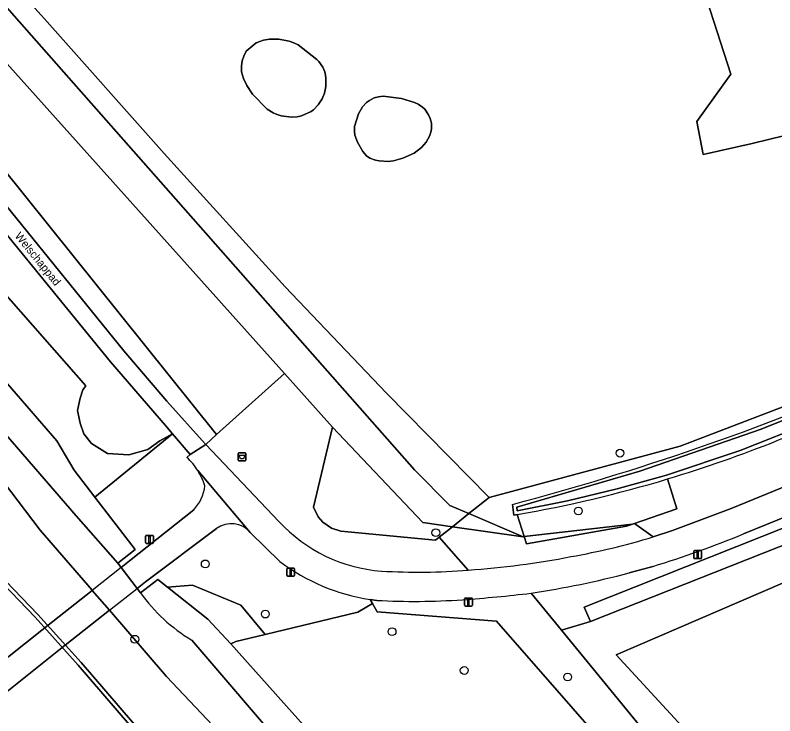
# Model space of a CAD drawing. Extents: x 156061 to 157804, y 383437 to 385640.
# Drawn here: x 157340 to 157434.9, y 383885.8 to 383973.3 of the extents above; entities that cross this region are included whole.
import ezdxf

# ---------------------------------------------------------------- set-up
doc = ezdxf.new("R2010")
doc.units = 0
for name, color, linetype in [('IMGEO_Afvalbak', 7, 'Continuous'), ('IMGEO_Berm_groen', 7, 'Continuous'), ('IMGEO_Boom', 7, 'Continuous'), ('IMGEO_Dek', 7, 'Continuous'), ('IMGEO_Fietspad_gesloten', 7, 'Continuous'), ('IMGEO_Fietspad_halfverhard', 7, 'Continuous'), ('IMGEO_Gemengd_bos', 7, 'Continuous'), ('IMGEO_Grasland_overig', 7, 'Continuous'), ('IMGEO_Groenvoorziening', 7, 'Continuous'), ('IMGEO_Hek', 7, 'Continuous'), ('IMGEO_Kademuur', 7, 'Continuous'), ('IMGEO_Lichtmast', 7, 'Continuous'), ('IMGEO_Loofbos', 7, 'Continuous'), ('IMGEO_Naaldbos', 7, 'Continuous'), ('IMGEO_Oever', 7, 'Continuous'), ('IMGEO_Openbare_ruimte_label', 7, 'Continuous'), ('IMGEO_Terreindeel_zand', 7, 'Continuous'), ('IMGEO_Waterloop', 7, 'Continuous')]:
    doc.layers.add(name, color=color, linetype=linetype)

msp = doc.modelspace()

# ---------------------------------------------------------------- linework, layer by layer
at = {"layer": 'IMGEO_Afvalbak'}
for p, q in [((157367.87, 383917.721), (157367.87, 383918.521)), ((157367.87, 383918.521), (157367.87, 383917.721)), ((157367.97, 383918.621), (157368.76, 383918.621)), ((157368.76, 383918.621), (157367.97, 383918.621)), ((157368.86, 383918.521), (157368.86, 383917.721)), ((157368.86, 383917.721), (157368.86, 383918.521)), ((157368.76, 383917.621), (157367.97, 383917.621)), ((157367.97, 383917.621), (157368.76, 383917.621))]:
    msp.add_line(p, q, dxfattribs=at)
msp.add_lwpolyline([(157368.013, 383918.335), (157368.717, 383918.335), (157368.568, 383917.865), (157368.162, 383917.865), (157368.013, 383918.335)], dxfattribs=at)
for centre, start, end in [((157367.97, 383918.521), 90, 180), ((157367.97, 383918.521), 90, 180), ((157368.76, 383918.521), 0, 90), ((157368.76, 383918.521), 360, 90), ((157367.97, 383917.721), 180, 270), ((157367.97, 383917.721), 180, 270), ((157368.76, 383917.721), 270, 0), ((157368.76, 383917.721), 270, 0)]:
    msp.add_arc(centre, 0.1, start, end, dxfattribs=at)
at = {"layer": 'IMGEO_Berm_groen'}
for points in [[(157290.106, 383993.809), (157348.861, 383926.973), (157348.496, 383926.485), (157348.148, 383925.443), (157347.803, 383923.91), (157348.13, 383922.337), (157348.587, 383921.007), (157349.58, 383919.805), (157351.567, 383918.549), (157354.208, 383918.372), (157356.584, 383919.046), (157358.1, 383920.118), (157359.668, 383920.985), (157358.8, 383922.017), (157351.927, 383929.987), (157331.108, 383955.485)], [(157517.733, 383943.702), (157500, 383936.506), (157462.003, 383921.087), (157431.048, 383908.507)], [(157421.548, 383915.365), (157422.713, 383911.64), (157417.276, 383909.769), (157417.146, 383909.724), (157417.419, 383909.786), (157419.731, 383908.129), (157422.151, 383908.928), (157429.498, 383911.684), (157449.933, 383920.053), (157500, 383940.38)], [(157404.491, 383901.096), (157408.277, 383896.475), (157411.901, 383897.544), (157411.136, 383899.333), (157500, 383934.673)], [(157419.699, 383904.431), (157416.735, 383903.615)]]:
    msp.add_lwpolyline(points, dxfattribs=at)
for centre, radius, start, end in [((157374.531, 384071.809), 163.356, 286.7274, 296.96883), ((157381.602, 384028.345), 129.639, 287.09005, 292.42152), ((157386.751, 384018.341), 118.579, 278.60403, 284.64687)]:
    msp.add_arc(centre, radius, start, end, dxfattribs=at)
at = {"layer": 'IMGEO_Boom'}
for centre in [(157415.602, 383918.588), (157410.384, 383911.353), (157392.578, 383908.65), (157363.773, 383904.747), (157371.281, 383898.483), (157387.117, 383896.285), (157354.975, 383895.338), (157396.133, 383891.442), (157409.055, 383890.62)]:
    msp.add_circle(centre, 0.489, dxfattribs=at)
at = {"layer": 'IMGEO_Dek'}
msp.add_lwpolyline([(157337.095, 383887.331), (157345.496, 383893.968), (157351.807, 383898.954), (157355.264, 383901.686), (157353.281, 383904.309), (157349.655, 383901.447), (157343.336, 383896.46), (157334.933, 383889.827), (157335.95, 383888.66)], close=True, dxfattribs=at)
at = {"layer": 'IMGEO_Fietspad_gesloten'}
for points in [[(157524.621, 383950.374), (157500, 383940.38), (157449.933, 383920.053), (157429.498, 383911.684), (157422.151, 383908.928), (157419.731, 383908.129)], [(157431.048, 383908.507), (157462.003, 383921.087), (157500, 383936.506)], [(157372.986, 383910.034), (157363.833, 383919.682), (157361.887, 383918.404), (157361.489, 383918.054)], [(157369.409, 383908.645), (157369.386, 383908.678), (157362.833, 383916.407)], [(157362.833, 383916.407), (157369.386, 383908.678), (157369.409, 383908.645), (157373.088, 383905.055)], [(157362.326, 383911.521), (157354.325, 383905.133), (157353.281, 383904.309), (157355.264, 383901.686), (157356.301, 383902.505), (157365.179, 383909.17)], [(157416.735, 383903.615), (157419.699, 383904.431)], [(157384.365, 383900.302), (157385.206, 383900.193)]]:
    msp.add_lwpolyline(points, dxfattribs=at)
msp.add_lwpolyline([(157337.095, 383887.331), (157345.496, 383893.968), (157351.807, 383898.954), (157355.264, 383901.686), (157353.281, 383904.309), (157349.655, 383901.447), (157343.336, 383896.46), (157334.933, 383889.827), (157335.95, 383888.66)], close=True, dxfattribs=at)
for centre, radius, start, end in [((157355.53, 383911.82), 8.624, 32.13573, 46.29516), ((157355.486, 383911.781), 8.682, 18.1348, 32.19859), ((157358.595, 383915.115), 5.181, 316.06818, 352.98861), ((157367.018, 383906.685), 3.092, 39.34518, 126.50482), ((157387.304, 383923.334), 19.542, 222.88964, 265.59021), ((157395.45, 383986.551), 82.095, 279.82457, 287.20359), ((157381.602, 384028.345), 129.639, 287.09005, 292.42152), ((157388.102, 383924.923), 24.903, 232.92198, 261.36938), ((157389.641, 384006.873), 103.135, 273.89195, 281.07825), ((157390.319, 383981.535), 77.816, 266.67172, 274.66019), ((157386.751, 384018.341), 118.579, 278.60403, 284.64687), ((157383.208, 384078.229), 178.408, 274.07957, 276.85145), ((157389.883, 383988.669), 88.599, 266.97395, 273.89399)]:
    msp.add_arc(centre, radius, start, end, dxfattribs=at)
at = {"layer": 'IMGEO_Fietspad_halfverhard'}
msp.add_lwpolyline([(157237.284, 384056.657), (157244.448, 384048.492), (157247.832, 384044.707), (157258.966, 384032.481), (157270.566, 384020.689), (157270.958, 384020.289), (157290.747, 384000.096), (157290.837, 384000), (157295.593, 383994.904), (157306.477, 383982.754), (157317.899, 383970.658), (157322.769, 383965.414), (157327.304, 383960.078), (157331.108, 383955.485), (157351.927, 383929.987), (157358.8, 383922.017), (157359.668, 383920.985), (157361.887, 383918.404), (157363.833, 383919.682), (157363.756, 383919.763), (157358.967, 383925.076), (157353.604, 383931.382), (157332.793, 383957.006), (157329.258, 383961.307)], dxfattribs=at)
at = {"layer": 'IMGEO_Gemengd_bos'}
msp.add_lwpolyline([(157361.489, 383918.054), (157361.887, 383918.404), (157359.668, 383920.985), (157349.992, 383913.096), (157355.031, 383906.528), (157352.864, 383904.861), (157353.281, 383904.309), (157354.325, 383905.133), (157362.326, 383911.521)], dxfattribs=at)
for centre, radius, start, end in [((157355.53, 383911.82), 8.624, 32.13573, 46.29516), ((157355.486, 383911.781), 8.682, 18.1348, 32.19859), ((157358.595, 383915.115), 5.181, 316.06818, 352.98861)]:
    msp.add_arc(centre, radius, start, end, dxfattribs=at)
at = {"layer": 'IMGEO_Grasland_overig'}
msp.add_lwpolyline([(157329.258, 383961.307), (157332.793, 383957.006), (157353.604, 383931.382), (157358.967, 383925.076), (157363.756, 383919.763), (157363.833, 383919.682), (157365.199, 383920.902), (157335.251, 383958.186), (157331.438, 383962.58), (157296.37, 384001.71), (157240.495, 384061.731), (157146.719, 384164.626)], dxfattribs=at)
at = {"layer": 'IMGEO_Groenvoorziening'}
for points in [[(157319.021, 384000), (157343.685, 383972.814), (157358.656, 383956.013), (157373.771, 383939.341), (157386.408, 383926.066), (157399.254, 383913.036), (157423.095, 383919.456), (157447.613, 383928.815), (157500, 383950.076), (157519.267, 383957.895), (157500, 383980.868), (157483.794, 384000), (157456.407, 384032.182), (157446.051, 384043.687), (157399.115, 384096.659)], [(157321.573, 383986.862), (157333.938, 383972.825), (157373.665, 383928.526), (157379.668, 383921.831), (157390.94, 383909.911), (157394.652, 383909.39), (157396.723, 383911.031), (157394.317, 383912.055), (157389.924, 383916.518), (157316.258, 384000), (157288.578, 384031.368)], [(157259.05, 384018.85), (157260.212, 384017.373), (157254.441, 384012.397), (157256.697, 384009.014), (157257.598, 384007.867), (157258.641, 384006.717), (157266.075, 384000), (157268.905, 383997.104), (157270.884, 383994.915), (157273.88, 383991.298), (157276.328, 383988.037), (157301.532, 383958.337), (157326.744, 383930.517), (157343.156, 383908.979), (157349.647, 383901.456), (157349.655, 383901.447), (157351.799, 383898.963), (157351.807, 383898.954), (157358.929, 383890.7), (157378.47, 383870.021), (157418.163, 383824.392), (157421.114, 383826.358), (157362.085, 383895.228)], [(157330.198, 383937.438), (157345.219, 383920.112), (157347.414, 383916.456), (157349.992, 383913.096), (157359.668, 383920.985), (157358.1, 383920.118), (157356.584, 383919.046), (157354.208, 383918.372), (157351.567, 383918.549), (157349.58, 383919.805), (157348.587, 383921.007), (157348.13, 383922.337), (157347.803, 383923.91), (157348.148, 383925.443), (157348.496, 383926.485), (157348.861, 383926.973), (157290.106, 383993.809)], [(157355.684, 383901.129), (157355.264, 383901.686), (157353.281, 383904.309), (157352.864, 383904.861), (157347.66, 383910.767), (157300.441, 383965.274), (157276.216, 383992.1)], [(157450.713, 383977.003), (157457.725, 383967.903), (157453.382, 383965.1), (157446.356, 383961.596), (157438.214, 383958.778), (157432.126, 383957.255), (157425.984, 383955.897), (157425.189, 383959.996), (157429.466, 383965.917), (157424.723, 383980.523)], [(157447.918, 383927.963), (157500, 383948.868), (157521.181, 383957.37), (157520.382, 383958.304), (157519.267, 383957.895), (157500, 383950.076), (157447.613, 383928.815), (157423.095, 383919.456), (157399.254, 383913.036), (157396.723, 383911.031), (157403.488, 383908.15), (157403.622, 383908.165), (157402.728, 383910.902), (157402.336, 383910.834), (157402.149, 383912.174)], [(157379.668, 383921.831), (157373.665, 383928.526), (157365.199, 383920.902), (157363.833, 383919.682), (157372.986, 383910.034)], [(157396.641, 383903.976), (157392.994, 383908.076), (157392.532, 383907.71), (157380.72, 383908.85), (157379.556, 383909.214), (157378.458, 383909.97), (157377.881, 383910.648), (157377.309, 383911.852), (157379.668, 383921.831)], [(157419.731, 383908.129), (157417.419, 383909.786), (157417.146, 383909.724), (157416.424, 383909.476), (157403.917, 383907.261), (157403.622, 383908.165), (157403.488, 383908.15), (157394.652, 383909.39), (157392.994, 383908.076), (157396.641, 383903.976)], [(157365.179, 383909.17), (157356.301, 383902.505), (157355.264, 383901.686), (157355.684, 383901.129), (157357.85, 383902.812), (157359.057, 383901.853), (157362.189, 383902.088), (157368.211, 383899.583), (157371.268, 383895.948), (157382.818, 383898.731), (157384.66, 383899.787), (157384.365, 383900.302)], [(157373.088, 383905.055), (157369.409, 383908.645)]]:
    msp.add_lwpolyline(points, dxfattribs=at)
for points in [[(157369.369, 383969.227), (157370.137, 383969.821), (157371.033, 383970.18), (157371.805, 383970.307), (157372.974, 383970.304), (157374.245, 383970.054), (157374.854, 383969.831), (157375.366, 383969.574), (157377.703, 383967.764), (157377.945, 383967.516), (157378.461, 383966.795), (157378.71, 383966.201), (157378.799, 383965.803), (157378.845, 383965.405), (157378.835, 383964.397), (157378.681, 383963.563), (157378.365, 383962.834), (157377.894, 383962.103), (157377.28, 383961.45), (157376.992, 383961.253), (157375.808, 383960.721), (157375.274, 383960.587), (157374.539, 383960.542), (157373.249, 383960.728), (157372.631, 383960.922), (157372.261, 383961.086), (157371.52, 383961.554), (157369.697, 383963.427), (157368.962, 383964.494), (157368.538, 383965.373), (157368.308, 383966.208), (157368.283, 383966.945), (157368.387, 383967.59), (157368.576, 383968.178), (157368.9, 383968.788)], [(157382.902, 383960.984), (157383.408, 383961.84), (157383.908, 383962.362), (157384.279, 383962.633), (157384.899, 383962.948), (157385.437, 383963.102), (157386.017, 383963.157), (157388.296, 383962.878), (157389.937, 383962.384), (157390.378, 383962.174), (157390.935, 383961.812), (157391.229, 383961.533), (157391.67, 383960.845), (157391.87, 383960.389), (157392.024, 383959.802), (157392.024, 383959.075), (157391.962, 383958.696), (157391.804, 383958.176), (157391.373, 383957.411), (157390.797, 383956.76), (157389.888, 383956.063), (157388.463, 383955.408), (157387.295, 383955.082), (157386.648, 383955.02), (157385.503, 383955.081), (157385.056, 383955.169), (157384.357, 383955.436), (157383.939, 383955.737), (157383.458, 383956.278), (157382.817, 383957.445), (157382.472, 383958.306), (157382.405, 383958.758), (157382.434, 383959.396)], [(157439.309, 383893.417), (157437.388, 383898.79), (157435.922, 383902.34), (157415.123, 383893.383), (157447.044, 383858.693), (157444.358, 383865.362), (157444.192, 383865.769), (157442.101, 383870.32), (157448.155, 383872.803), (157446.319, 383877.47), (157446.131, 383877.95), (157444.426, 383881.557)]]:
    msp.add_lwpolyline(points, close=True, dxfattribs=at)
for centre, radius, start, end in [((157316.527, 384234.606), 333.607, 284.87169, 293.19426), ((157367.018, 383906.685), 3.092, 39.34518, 126.50482), ((157387.304, 383923.334), 19.542, 222.88964, 265.59021), ((157395.45, 383986.551), 82.095, 279.82457, 287.20359), ((157388.102, 383924.923), 24.903, 232.92198, 261.36938), ((157389.641, 384006.873), 103.135, 273.89195, 281.07825), ((157390.319, 383981.535), 77.816, 266.67172, 274.66019), ((157373.138, 383913.639), 21.474, 215.63194, 239.02294)]:
    msp.add_arc(centre, radius, start, end, dxfattribs=at)
at = {"layer": 'IMGEO_Hek'}
for points in [[(157286.321, 384037.046), (157293.191, 384028.117), (157297.009, 384023.537), (157304.069, 384015.719), (157311.428, 384008.182), (157319.021, 384000), (157343.685, 383972.814), (157358.656, 383956.013), (157373.771, 383939.341), (157386.408, 383926.066), (157399.254, 383913.036)], [(157354.325, 383905.133), (157353.281, 383904.309)], [(157353.281, 383904.309), (157349.655, 383901.447)], [(157355.264, 383901.686), (157356.301, 383902.505)], [(157343.336, 383896.46), (157349.655, 383901.447)], [(157351.807, 383898.954), (157355.264, 383901.686)], [(157351.807, 383898.954), (157345.496, 383893.968)], [(157334.933, 383889.827), (157343.336, 383896.46)], [(157345.496, 383893.968), (157337.095, 383887.331)]]:
    msp.add_lwpolyline(points, dxfattribs=at)
at = {"layer": 'IMGEO_Kademuur'}
msp.add_lwpolyline([(157334.427, 383906.469), (157342.504, 383898.09), (157347.902, 383892.099), (157355.831, 383882.852), (157361.751, 383875.986), (157371.475, 383864.77), (157377.728, 383857.417), (157378.109, 383857.741), (157376.665, 383859.438), (157375.248, 383861.105), (157371.854, 383865.096), (157362.129, 383876.313), (157356.21, 383883.178), (157348.278, 383892.43), (157342.87, 383898.431), (157334.791, 383906.812)], dxfattribs=at)
at = {"layer": 'IMGEO_Lichtmast'}
for p, q in [((157356.3, 383907.407), (157356.3, 383908.207)), ((157356.3, 383908.207), (157356.3, 383907.407)), ((157356.4, 383908.307), (157357.19, 383908.307)), ((157357.19, 383908.307), (157356.4, 383908.307)), ((157357.29, 383908.207), (157357.29, 383907.407)), ((157357.29, 383907.407), (157357.29, 383908.207)), ((157357.19, 383907.307), (157356.4, 383907.307)), ((157356.4, 383907.307), (157357.19, 383907.307)), ((157424.809, 383905.504), (157424.809, 383906.304)), ((157424.809, 383906.304), (157424.809, 383905.504)), ((157424.909, 383906.404), (157425.699, 383906.404)), ((157425.699, 383906.404), (157424.909, 383906.404)), ((157425.799, 383906.304), (157425.799, 383905.504)), ((157425.799, 383905.504), (157425.799, 383906.304)), ((157425.699, 383905.404), (157424.909, 383905.404)), ((157424.909, 383905.404), (157425.699, 383905.404)), ((157373.949, 383903.319), (157373.949, 383904.119)), ((157373.949, 383904.119), (157373.949, 383903.319)), ((157374.049, 383904.219), (157374.839, 383904.219)), ((157374.839, 383904.219), (157374.049, 383904.219)), ((157374.939, 383904.119), (157374.939, 383903.319)), ((157374.939, 383903.319), (157374.939, 383904.119)), ((157374.839, 383903.219), (157374.049, 383903.219)), ((157374.049, 383903.219), (157374.839, 383903.219)), ((157396.159, 383899.588), (157396.159, 383900.388)), ((157396.159, 383900.388), (157396.159, 383899.588)), ((157396.259, 383900.488), (157397.049, 383900.488)), ((157397.049, 383900.488), (157396.259, 383900.488)), ((157397.149, 383900.388), (157397.149, 383899.588)), ((157397.149, 383899.588), (157397.149, 383900.388)), ((157397.049, 383899.488), (157396.259, 383899.488)), ((157396.259, 383899.488), (157397.049, 383899.488))]:
    msp.add_line(p, q, dxfattribs=at)
for points in [[(157356.72, 383908.182), (157356.87, 383908.182), (157356.87, 383907.432), (157356.72, 383907.432), (157356.72, 383908.182)], [(157425.229, 383906.279), (157425.379, 383906.279), (157425.379, 383905.529), (157425.229, 383905.529), (157425.229, 383906.279)], [(157374.369, 383904.094), (157374.519, 383904.094), (157374.519, 383903.344), (157374.369, 383903.344), (157374.369, 383904.094)], [(157396.579, 383900.363), (157396.729, 383900.363), (157396.729, 383899.613), (157396.579, 383899.613), (157396.579, 383900.363)]]:
    msp.add_lwpolyline(points, dxfattribs=at)
for centre, start, end in [((157356.4, 383908.207), 90, 180), ((157356.4, 383908.207), 90, 180), ((157357.19, 383908.207), 0, 90), ((157357.19, 383908.207), 360, 90), ((157356.4, 383907.407), 180, 270), ((157356.4, 383907.407), 180, 270), ((157357.19, 383907.407), 270, 0), ((157357.19, 383907.407), 270, 0), ((157424.909, 383906.304), 90, 180), ((157424.909, 383906.304), 90, 180), ((157425.699, 383906.304), 0, 90), ((157425.699, 383906.304), 360, 90), ((157424.909, 383905.504), 180, 270), ((157424.909, 383905.504), 180, 270), ((157425.699, 383905.504), 270, 0), ((157425.699, 383905.504), 270, 0), ((157374.049, 383904.119), 90, 180), ((157374.049, 383904.119), 90, 180), ((157374.839, 383904.119), 0, 90), ((157374.839, 383904.119), 360, 90), ((157374.049, 383903.319), 180, 270), ((157374.049, 383903.319), 180, 270), ((157374.839, 383903.319), 270, 0), ((157374.839, 383903.319), 270, 0), ((157396.259, 383900.388), 90, 180), ((157396.259, 383900.388), 90, 180), ((157397.049, 383900.388), 0, 90), ((157397.049, 383900.388), 360, 90), ((157396.259, 383899.588), 180, 270), ((157396.259, 383899.588), 180, 270), ((157397.049, 383899.588), 270, 0), ((157397.049, 383899.588), 270, 0)]:
    msp.add_arc(centre, 0.1, start, end, dxfattribs=at)
at = {"layer": 'IMGEO_Loofbos'}
for points in [[(157019.79, 384303.654), (157021.328, 384305.497), (157070.215, 384252.238), (157146.719, 384164.626), (157240.495, 384061.731), (157296.37, 384001.71), (157331.438, 383962.58), (157335.251, 383958.186), (157365.199, 383920.902), (157373.665, 383928.526), (157333.938, 383972.825), (157321.573, 383986.862)], [(157288.578, 384031.368), (157316.258, 384000), (157389.924, 383916.518), (157394.317, 383912.055), (157396.723, 383911.031), (157399.254, 383913.036), (157386.408, 383926.066), (157373.771, 383939.341), (157358.656, 383956.013), (157343.685, 383972.814), (157319.021, 384000), (157311.428, 384008.182), (157304.069, 384015.719), (157297.009, 384023.537), (157293.191, 384028.117), (157286.321, 384037.046)], [(157276.216, 383992.1), (157300.441, 383965.274), (157347.66, 383910.767), (157352.864, 383904.861), (157355.031, 383906.528), (157349.992, 383913.096), (157347.414, 383916.456), (157345.219, 383920.112), (157330.198, 383937.438), (157307.422, 383964.665), (157281.279, 383994.597)], [(157535.579, 383945.559), (157534.472, 383945.34), (157533.99, 383945.18), (157531.575, 383944.872), (157500, 383932.385), (157411.901, 383897.544), (157408.277, 383896.475), (157454.233, 383840.382), (157434.932, 383831.832), (157436.986, 383829.444), (157463.791, 383840.494), (157458.124, 383847.536), (157457.535, 383847.292), (157452.513, 383845.217), (157450.109, 383851.084), (157447.044, 383858.693), (157415.123, 383893.383)], [(157415.123, 383893.383), (157435.922, 383902.34), (157446.88, 383906.866), (157457.995, 383911.456), (157469.01, 383916.005), (157480.093, 383920.582), (157491.234, 383925.184), (157498.845, 383928.327), (157502.401, 383929.795), (157513.277, 383934.287), (157517.898, 383936.195), (157517.925, 383936.129), (157536.048, 383943.515), (157545.849, 383924.57), (157546.205, 383923.882), (157547.146, 383924.269)], [(157378.47, 383870.021), (157358.929, 383890.7), (157351.807, 383898.954), (157351.799, 383898.963), (157349.655, 383901.447), (157349.647, 383901.456), (157343.156, 383908.979), (157326.744, 383930.517)], [(157402.728, 383910.902), (157403.622, 383908.165), (157417.146, 383909.724), (157417.276, 383909.769), (157422.713, 383911.64), (157421.548, 383915.365)], [(157334.791, 383906.812), (157342.87, 383898.431), (157348.278, 383892.43), (157356.21, 383883.178)], [(157362.085, 383895.228), (157421.114, 383826.358), (157425.485, 383829.271), (157366.965, 383894.748), (157364.108, 383897.839), (157359.057, 383901.853), (157357.85, 383902.812), (157355.684, 383901.129)], [(157385.206, 383900.193), (157384.365, 383900.302), (157384.66, 383899.787), (157385.247, 383898.76), (157400.157, 383897.578), (157448.346, 383842.522), (157426.548, 383832.918), (157431.477, 383827.173), (157436.986, 383829.444), (157434.932, 383831.832), (157454.233, 383840.382), (157408.277, 383896.475), (157404.491, 383901.096)]]:
    msp.add_lwpolyline(points, dxfattribs=at)
for points in [[(157377.309, 383911.852), (157377.881, 383910.648), (157378.458, 383909.97), (157379.556, 383909.214), (157380.72, 383908.85), (157392.532, 383907.71), (157392.994, 383908.076), (157394.652, 383909.39), (157390.94, 383909.911), (157379.668, 383921.831)], [(157403.488, 383908.15), (157396.723, 383911.031), (157394.652, 383909.39)], [(157403.622, 383908.165), (157403.917, 383907.261), (157416.424, 383909.476), (157417.146, 383909.724)], [(157371.268, 383895.948), (157368.211, 383899.583), (157362.189, 383902.088), (157359.057, 383901.853), (157364.108, 383897.839), (157366.965, 383894.748), (157367.599, 383895.069)], [(157425.485, 383829.271), (157427.085, 383830.337), (157430.594, 383826.809), (157431.477, 383827.173), (157426.548, 383832.918), (157448.346, 383842.522), (157400.157, 383897.578), (157385.247, 383898.76), (157384.66, 383899.787), (157382.818, 383898.731), (157371.268, 383895.948), (157367.599, 383895.069), (157366.965, 383894.748)]]:
    msp.add_lwpolyline(points, close=True, dxfattribs=at)
for centre, radius, start, end in [((157374.471, 384071.973), 163.531, 279.9504, 286.73113), ((157373.138, 383913.639), 21.474, 215.63194, 239.02294), ((157383.208, 384078.229), 178.408, 274.07957, 276.85145), ((157389.883, 383988.669), 88.599, 266.97395, 273.89399)]:
    msp.add_arc(centre, radius, start, end, dxfattribs=at)
at = {"layer": 'IMGEO_Naaldbos'}
msp.add_lwpolyline([(157427.782, 384002.36), (157428.163, 383997.333), (157425.956, 383992.382), (157421.543, 383990.173), (157416.026, 383990.498), (157424.723, 383980.523), (157429.466, 383965.917), (157425.189, 383959.996), (157425.984, 383955.897), (157432.126, 383957.255), (157438.214, 383958.778), (157446.356, 383961.596), (157453.382, 383965.1), (157457.725, 383967.903), (157450.713, 383977.003)], close=True, dxfattribs=at)
at = {"layer": 'IMGEO_Oever'}
for points in [[(157439.633, 383922.513), (157430.62, 383918.898), (157421.409, 383915.828), (157415.247, 383914.107), (157409.023, 383912.629), (157402.746, 383911.396), (157402.687, 383911.817), (157418.071, 383916.321), (157433.221, 383921.559), (157448.103, 383927.517)], [(157402.149, 383912.174), (157402.336, 383910.834), (157402.728, 383910.902)]]:
    msp.add_lwpolyline(points, dxfattribs=at)
for centre, radius, start, end in [((157316.527, 384234.606), 333.607, 284.87169, 293.19426), ((157374.531, 384071.809), 163.356, 286.7274, 296.96883), ((157374.471, 384071.973), 163.531, 279.9504, 286.73113)]:
    msp.add_arc(centre, radius, start, end, dxfattribs=at)
at = {"layer": 'IMGEO_Terreindeel_zand'}
for points in [[(157369.369, 383969.227), (157368.9, 383968.788), (157368.576, 383968.178), (157368.387, 383967.59), (157368.283, 383966.945), (157368.308, 383966.208), (157368.538, 383965.373), (157368.962, 383964.494), (157369.697, 383963.427), (157371.52, 383961.554), (157372.261, 383961.086), (157372.631, 383960.922), (157373.249, 383960.728), (157374.539, 383960.542), (157375.274, 383960.587), (157375.808, 383960.721), (157376.992, 383961.253), (157377.28, 383961.45), (157377.894, 383962.103), (157378.365, 383962.834), (157378.681, 383963.563), (157378.835, 383964.397), (157378.845, 383965.405), (157378.799, 383965.803), (157378.71, 383966.201), (157378.461, 383966.795), (157377.945, 383967.516), (157377.703, 383967.764), (157375.366, 383969.574), (157374.854, 383969.831), (157374.245, 383970.054), (157372.974, 383970.304), (157371.805, 383970.307), (157371.033, 383970.18), (157370.137, 383969.821)], [(157382.902, 383960.984), (157382.434, 383959.396), (157382.405, 383958.758), (157382.472, 383958.306), (157382.817, 383957.445), (157383.458, 383956.278), (157383.939, 383955.737), (157384.357, 383955.436), (157385.056, 383955.169), (157385.503, 383955.081), (157386.648, 383955.02), (157387.295, 383955.082), (157388.463, 383955.408), (157389.888, 383956.063), (157390.797, 383956.76), (157391.373, 383957.411), (157391.804, 383958.176), (157391.962, 383958.696), (157392.024, 383959.075), (157392.024, 383959.802), (157391.87, 383960.389), (157391.67, 383960.845), (157391.229, 383961.533), (157390.935, 383961.812), (157390.378, 383962.174), (157389.937, 383962.384), (157388.296, 383962.878), (157386.017, 383963.157), (157385.437, 383963.102), (157384.899, 383962.948), (157384.279, 383962.633), (157383.908, 383962.362), (157383.408, 383961.84)]]:
    msp.add_lwpolyline(points, close=True, dxfattribs=at)
at = {"layer": 'IMGEO_Waterloop'}
for points in [[(157530.633, 383946.855), (157500, 383934.673), (157411.136, 383899.333), (157411.901, 383897.544), (157500, 383932.385), (157531.575, 383944.872)], [(157448.103, 383927.517), (157433.221, 383921.559), (157418.071, 383916.321), (157402.687, 383911.817), (157402.746, 383911.396), (157409.023, 383912.629), (157415.247, 383914.107), (157421.409, 383915.828), (157430.62, 383918.898), (157439.633, 383922.513)], [(157425.947, 383801.7), (157410.641, 383819.379), (157408.067, 383822.352), (157399.516, 383832.27), (157389.522, 383843.804), (157381.147, 383853.407), (157381.524, 383853.736), (157382.904, 383852.153), (157383.506, 383852.604), (157377.269, 383859.993), (157376.665, 383859.438), (157378.109, 383857.741), (157377.728, 383857.417), (157371.475, 383864.77), (157361.751, 383875.986), (157355.831, 383882.852), (157347.902, 383892.099), (157342.504, 383898.09), (157334.427, 383906.469)]]:
    msp.add_lwpolyline(points, dxfattribs=at)

# ---------------------------------------------------------------- texts
at = {"layer": 'IMGEO_Openbare_ruimte_label'}
msp.add_text('Welschappad', height=1, rotation=309.11609, dxfattribs=at).set_placement((157339.914, 383945.68))

doc.saveas('drawing.dxf')
